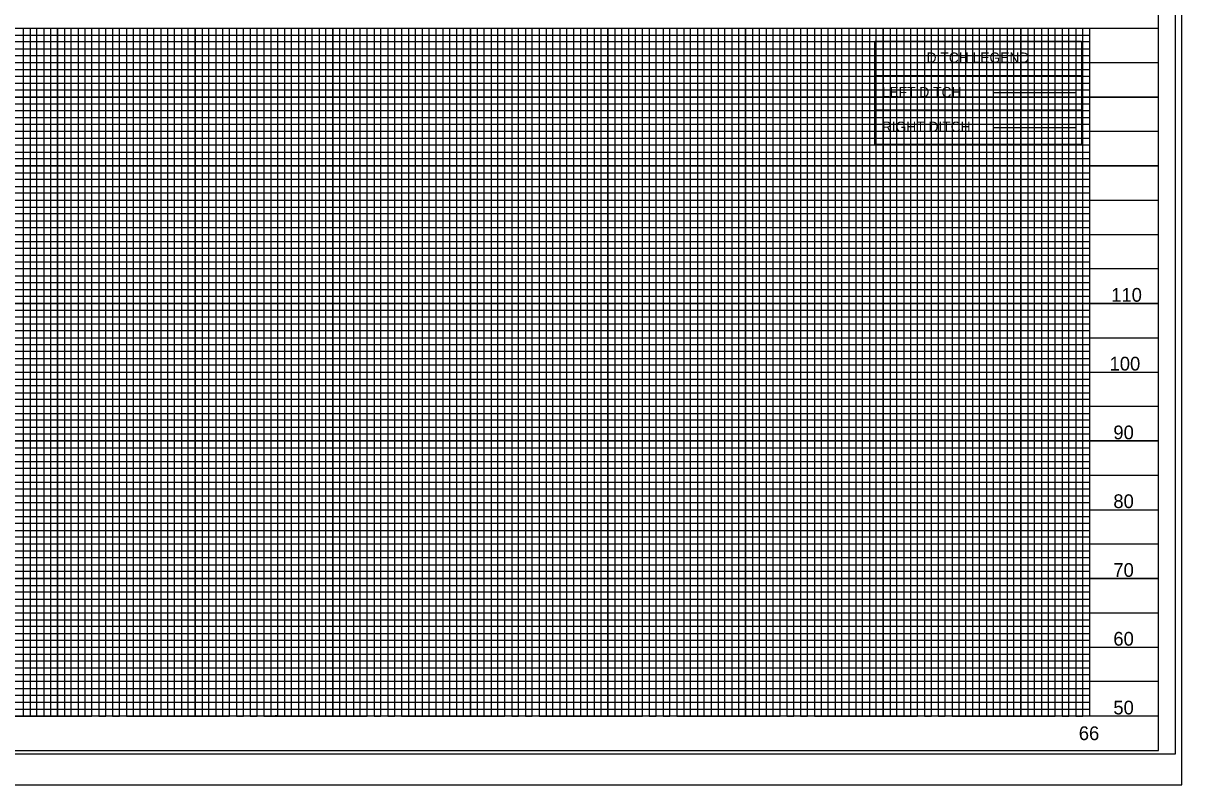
# Model space of a CAD drawing. Extents: x 2367101 to 2368930, y 803279 to 808979.
# Drawn here: x 2367943 to 2368785, y 803279 to 803833 of the extents above; entities that cross this region are included whole.
import ezdxf

# ---------------------------------------------------------------- set-up
doc = ezdxf.new("R2010")
doc.units = 0
for name, color, linetype in [('Old_Level_11', 7, 'Continuous'), ('Old_Level_12', 7, 'Continuous'), ('Old_Level_13', 7, 'Continuous'), ('Old_Level_15', 7, 'Continuous'), ('Old_Level_17', 7, 'Continuous'), ('Old_Level_19', 7, 'Continuous'), ('Old_Level_4', 7, 'Continuous'), ('Old_Level_5', 7, 'Continuous'), ('Old_Level_6', 7, 'Continuous'), ('Old_Level_60', 7, 'Continuous'), ('Old_Level_8', 7, 'Continuous'), ('Old_Level_9', 7, 'Continuous'), ('Text', 7, 'Continuous')]:
    doc.layers.add(name, color=color, linetype=linetype)

msp = doc.modelspace()

# ---------------------------------------------------------------- linework, layer by layer
at = {"layer": 'Old_Level_11'}
for p, q in [((2367967.97, 803828.98), (2368017.97, 803828.98)), ((2368067.97, 803828.98), (2368117.97, 803828.98)), ((2368167.97, 803828.98), (2368217.97, 803828.98)), ((2368267.97, 803828.98), (2368317.97, 803828.98)), ((2368367.97, 803828.98), (2368417.97, 803828.98)), ((2368467.97, 803828.98), (2368517.97, 803828.98)), ((2368567.97, 803828.98), (2368617.97, 803828.98)), ((2368667.97, 803828.98), (2368717.97, 803828.98)), ((2368667.97, 803328.98), (2368667.97, 803328.98))]:
    msp.add_line(p, q, dxfattribs=at)
for points in [[(2367917.97, 803328.98), (2367967.97, 803328.98), (2367967.97, 803828.98), (2368017.97, 803828.98), (2368017.97, 803328.98), (2368067.97, 803328.98), (2368067.97, 803828.98), (2368117.97, 803828.98), (2368117.97, 803328.98), (2368167.97, 803328.98), (2368167.97, 803828.98), (2368217.97, 803828.98), (2368217.97, 803328.98), (2368267.97, 803328.98), (2368267.97, 803828.98), (2368317.97, 803828.98), (2368317.97, 803328.98), (2368367.97, 803328.98), (2368367.97, 803828.98), (2368417.97, 803828.98), (2368417.97, 803328.98), (2368467.97, 803328.98), (2368467.97, 803828.98), (2368517.97, 803828.98), (2368517.97, 803328.98), (2368567.97, 803328.98), (2368567.97, 803828.98), (2368617.97, 803828.98), (2368617.97, 803328.98), (2368667.97, 803328.98), (2368667.97, 803328.98), (2368667.97, 803828.98), (2368717.97, 803828.98), (2368717.97, 803328.98)], [(2368767.97, 803778.98), (2367267.97, 803778.98)], [(2368767.97, 803728.98), (2367267.97, 803728.98), (2367267.97, 803678.98), (2368767.97, 803678.98)], [(2368767.97, 803628.98), (2367267.97, 803628.98), (2367267.97, 803578.98), (2368767.97, 803578.98)], [(2368767.97, 803528.98), (2367267.97, 803528.98), (2367267.97, 803478.98), (2368767.97, 803478.98)], [(2368767.97, 803428.98), (2367267.97, 803428.98), (2367267.97, 803428.98), (2367267.97, 803378.98), (2368767.97, 803378.98)], [(2368767.97, 803328.98), (2367267.97, 803328.98)]]:
    msp.add_lwpolyline(points, dxfattribs=at)
at = {"layer": 'Old_Level_12'}
for points in [[(2367892.97, 803828.98), (2367942.97, 803828.98), (2367942.97, 803328.98), (2367992.97, 803328.98), (2367992.97, 803828.98), (2368042.97, 803828.98), (2368042.97, 803328.98), (2368092.97, 803328.98), (2368092.97, 803828.98), (2368142.97, 803828.98), (2368142.97, 803328.98), (2368192.97, 803328.98), (2368192.97, 803828.98), (2368242.97, 803828.98), (2368242.97, 803328.98), (2368292.97, 803328.98), (2368292.97, 803828.98), (2368342.97, 803828.98), (2368342.97, 803328.98), (2368392.97, 803328.98), (2368392.97, 803828.98), (2368442.97, 803828.98), (2368442.97, 803328.98), (2368492.97, 803328.98), (2368492.97, 803828.98), (2368542.97, 803828.98), (2368542.97, 803328.98), (2368592.97, 803328.98), (2368592.97, 803828.98), (2368642.97, 803828.98), (2368642.97, 803328.98), (2368692.97, 803328.98), (2368692.97, 803828.98)], [(2367267.97, 803803.98), (2368767.97, 803803.98)], [(2368767.97, 803753.98), (2367267.97, 803753.98), (2367267.97, 803703.98), (2368767.97, 803703.98)], [(2368767.97, 803653.98), (2367267.97, 803653.98), (2367267.97, 803603.98), (2368767.97, 803603.98)], [(2368767.97, 803553.98), (2367267.97, 803553.98), (2367267.97, 803503.98), (2368767.97, 803503.98)], [(2368767.97, 803453.98), (2367267.97, 803453.98), (2367267.97, 803403.98), (2368767.97, 803403.98)], [(2368767.97, 803353.98), (2367267.97, 803353.98)]]:
    msp.add_lwpolyline(points, dxfattribs=at)
at = {"layer": 'Old_Level_13'}
for p, q in [((2367267.97, 803828.98), (2368767.86, 803828.98)), ((2367967.97, 803828.98), (2367967.97, 803328.98)), ((2368017.97, 803828.98), (2368017.97, 803328.98)), ((2368067.97, 803828.98), (2368067.97, 803328.98)), ((2368117.97, 803828.98), (2368117.97, 803328.98)), ((2368167.97, 803828.98), (2368167.97, 803328.98)), ((2368217.97, 803828.98), (2368217.97, 803328.98)), ((2368267.97, 803828.98), (2368267.97, 803328.98)), ((2368317.97, 803828.98), (2368317.97, 803328.98)), ((2368367.97, 803828.98), (2368367.97, 803328.98)), ((2368417.97, 803828.98), (2368417.97, 803328.98)), ((2368467.97, 803828.98), (2368467.97, 803328.98)), ((2368517.97, 803828.98), (2368517.97, 803328.98)), ((2368567.97, 803828.98), (2368567.97, 803328.98)), ((2368617.97, 803828.98), (2368617.97, 803328.98)), ((2368667.97, 803828.98), (2368667.97, 803328.98)), ((2368717.97, 803828.98), (2368717.97, 803328.98)), ((2367267.97, 803778.98), (2368767.86, 803778.98)), ((2367267.97, 803728.98), (2368767.86, 803728.98)), ((2367267.97, 803678.98), (2368767.86, 803678.98)), ((2367267.97, 803628.98), (2368767.86, 803628.98)), ((2367267.97, 803578.98), (2368767.86, 803578.98)), ((2367267.97, 803528.98), (2368767.86, 803528.98)), ((2367267.97, 803478.98), (2368767.86, 803478.98)), ((2367267.97, 803428.98), (2368767.86, 803428.98)), ((2367267.97, 803378.98), (2368767.86, 803378.98))]:
    msp.add_line(p, q, dxfattribs=at)
at = {"layer": 'Old_Level_15'}
msp.add_line((2367100.97, 803278.98), (2368784.97, 803278.98), dxfattribs=at)
at = {"layer": 'Old_Level_4'}
msp.add_lwpolyline([(2367113.97, 803301.43), (2368780.47, 803301.43), (2368780.47, 804356.53), (2367113.97, 804356.53)], close=True, dxfattribs=at)
at = {"layer": 'Old_Level_5'}
msp.add_lwpolyline([(2367317.97, 803828.98), (2368717.97, 803828.98), (2368717.97, 803328.98), (2367317.97, 803328.98)], close=True, dxfattribs=at)
at = {"layer": 'Old_Level_6'}
msp.add_lwpolyline([(2367100.97, 803278.98), (2368784.97, 803278.98), (2368784.97, 804378.98), (2367100.97, 804378.98)], close=True, dxfattribs=at)
at = {"layer": 'Old_Level_60'}
for points in [[(2368561.98, 803819.49), (2368711.98, 803819.49), (2368711.98, 803794.49), (2368561.98, 803794.49)], [(2368561.98, 803794.49), (2368711.98, 803794.49), (2368711.98, 803769.49), (2368561.98, 803769.49)], [(2368561.98, 803769.49), (2368711.98, 803769.49), (2368711.98, 803744.49), (2368561.98, 803744.49)]]:
    msp.add_lwpolyline(points, close=True, dxfattribs=at)
at = {"layer": 'Old_Level_8'}
for p, q in [((2367317.97, 803823.98), (2368717.97, 803823.98)), ((2368717.97, 803818.98), (2367317.97, 803818.98)), ((2367317.97, 803813.98), (2368717.97, 803813.98)), ((2368717.97, 803808.98), (2367317.97, 803808.98)), ((2367317.97, 803798.98), (2368717.97, 803798.98)), ((2368717.97, 803793.98), (2367317.97, 803793.98)), ((2367317.97, 803788.98), (2368717.97, 803788.98)), ((2368717.97, 803783.98), (2367317.97, 803783.98)), ((2367317.97, 803773.98), (2368717.97, 803773.98)), ((2368717.97, 803768.98), (2367317.97, 803768.98)), ((2367317.97, 803763.98), (2368717.97, 803763.98)), ((2368717.97, 803758.98), (2367317.97, 803758.98)), ((2367317.97, 803748.98), (2368717.97, 803748.98)), ((2368717.97, 803743.98), (2367317.97, 803743.98)), ((2367317.97, 803738.98), (2368717.97, 803738.98)), ((2368717.97, 803733.98), (2367317.97, 803733.98)), ((2367317.97, 803723.98), (2368717.97, 803723.98)), ((2368717.97, 803718.98), (2367317.97, 803718.98)), ((2367317.97, 803713.98), (2368717.97, 803713.98)), ((2368717.97, 803708.98), (2367317.97, 803708.98)), ((2367317.97, 803698.98), (2368717.97, 803698.98)), ((2368717.97, 803693.98), (2367317.97, 803693.98)), ((2367317.97, 803688.98), (2368717.97, 803688.98)), ((2368717.97, 803683.98), (2367317.97, 803683.98)), ((2367317.97, 803673.98), (2368717.97, 803673.98)), ((2368717.97, 803668.98), (2367317.97, 803668.98)), ((2367317.97, 803663.98), (2368717.97, 803663.98)), ((2368717.97, 803658.98), (2367317.97, 803658.98)), ((2367317.97, 803648.98), (2368717.97, 803648.98)), ((2368717.97, 803643.98), (2367317.97, 803643.98)), ((2367317.97, 803638.98), (2368717.97, 803638.98)), ((2368717.97, 803633.98), (2367317.97, 803634.13)), ((2367317.97, 803623.98), (2368717.97, 803623.98)), ((2368717.97, 803618.98), (2367317.97, 803618.98)), ((2367317.97, 803613.98), (2368717.97, 803613.98)), ((2368717.97, 803608.98), (2367317.97, 803608.98)), ((2367317.97, 803598.98), (2368717.97, 803598.98)), ((2368717.97, 803593.98), (2367317.97, 803593.98)), ((2367317.97, 803588.98), (2368717.97, 803588.98)), ((2368717.97, 803583.98), (2367317.97, 803583.98)), ((2367317.97, 803573.98), (2368717.97, 803573.98)), ((2368717.97, 803568.98), (2367317.97, 803568.98)), ((2367317.97, 803563.98), (2368717.97, 803563.98)), ((2368717.97, 803558.98), (2367317.97, 803558.98)), ((2367317.97, 803548.98), (2368717.97, 803548.98)), ((2368717.97, 803543.98), (2367317.97, 803543.98)), ((2367317.97, 803538.98), (2368717.97, 803538.98)), ((2368717.97, 803533.98), (2367317.97, 803533.98)), ((2367317.97, 803523.98), (2368717.97, 803523.98)), ((2368717.97, 803518.98), (2367317.97, 803518.98)), ((2367317.97, 803513.98), (2368717.97, 803513.98)), ((2368717.97, 803508.98), (2367317.97, 803508.98)), ((2367317.97, 803498.98), (2368717.97, 803498.98)), ((2368717.97, 803493.98), (2367317.97, 803493.98)), ((2367317.97, 803488.98), (2368717.97, 803488.98)), ((2368717.97, 803483.98), (2367317.97, 803483.98)), ((2367317.97, 803473.98), (2368717.97, 803473.98)), ((2368717.97, 803468.98), (2367317.97, 803468.98)), ((2367317.97, 803463.98), (2368717.97, 803463.98)), ((2368717.97, 803458.98), (2367317.97, 803458.98)), ((2367317.97, 803448.98), (2368717.97, 803448.98)), ((2368717.97, 803443.98), (2367317.97, 803443.98)), ((2367317.97, 803438.98), (2368717.97, 803438.98)), ((2368717.97, 803433.98), (2367317.97, 803433.98)), ((2367317.97, 803423.98), (2368717.97, 803423.98)), ((2368717.97, 803418.98), (2367317.97, 803418.98)), ((2367317.97, 803413.98), (2368717.97, 803413.98)), ((2368717.97, 803408.98), (2367317.97, 803408.98)), ((2367317.97, 803398.98), (2368717.97, 803398.98)), ((2368717.97, 803393.98), (2367317.97, 803393.98)), ((2367317.97, 803388.98), (2368717.97, 803388.98)), ((2368717.97, 803383.98), (2367317.97, 803383.98)), ((2367317.97, 803373.98), (2368717.97, 803373.98)), ((2368717.97, 803368.98), (2367317.97, 803368.98)), ((2367317.97, 803363.98), (2368717.97, 803363.98)), ((2368717.97, 803358.98), (2367317.97, 803358.98)), ((2367317.97, 803348.98), (2368717.97, 803348.98)), ((2368717.97, 803343.98), (2367317.97, 803343.98)), ((2367317.97, 803338.98), (2368717.97, 803338.98)), ((2367317.97, 803333.98), (2368717.97, 803333.98)), ((2368717.97, 803333.98), (2368717.97, 803333.98))]:
    msp.add_line(p, q, dxfattribs=at)
for points in [[(2367937.97, 803828.98), (2367947.97, 803828.98), (2367947.97, 803328.98), (2367952.97, 803328.98), (2367952.97, 803828.98), (2367957.97, 803828.98), (2367957.97, 803328.98), (2367962.97, 803328.98), (2367962.97, 803828.98), (2367972.97, 803828.98), (2367972.97, 803328.98), (2367972.97, 803328.98), (2367977.97, 803328.98), (2367977.97, 803828.98), (2367982.97, 803828.98), (2367982.97, 803328.98), (2367987.97, 803328.98), (2367987.97, 803828.98), (2367997.97, 803828.98), (2367997.97, 803328.98), (2368002.97, 803328.98), (2368002.97, 803828.98), (2368007.97, 803828.98), (2368007.97, 803328.98), (2368012.97, 803328.98), (2368012.97, 803828.98), (2368022.97, 803828.98), (2368022.97, 803328.98), (2368027.97, 803328.98), (2368027.97, 803828.98), (2368032.97, 803828.98), (2368032.97, 803328.98), (2368037.97, 803328.98), (2368037.97, 803828.98), (2368047.97, 803828.98), (2368047.97, 803328.98), (2368052.97, 803328.98), (2368052.97, 803828.98), (2368057.97, 803828.98), (2368057.97, 803328.98), (2368062.97, 803328.98), (2368062.97, 803828.98), (2368072.97, 803828.98), (2368072.97, 803328.98), (2368077.97, 803328.98), (2368077.97, 803828.98), (2368082.97, 803828.98), (2368082.97, 803328.98), (2368087.97, 803328.98), (2368087.97, 803828.98), (2368097.97, 803828.98), (2368097.97, 803328.98), (2368102.97, 803328.98), (2368102.97, 803828.98), (2368107.97, 803828.98), (2368107.97, 803328.98), (2368112.97, 803328.98), (2368112.97, 803828.98), (2368122.97, 803828.98), (2368122.97, 803328.98), (2368127.67, 803329.53), (2368127.97, 803328.98), (2368127.97, 803828.98), (2368132.97, 803828.98), (2368132.97, 803328.98), (2368137.97, 803328.98), (2368137.97, 803828.98), (2368147.97, 803828.98), (2368147.97, 803328.98), (2368152.97, 803328.98)], [(2368152.97, 803328.98), (2368152.97, 803828.98), (2368157.97, 803828.98), (2368157.97, 803328.98), (2368162.97, 803328.98), (2368162.97, 803828.98), (2368172.97, 803828.98), (2368172.97, 803328.98), (2368177.97, 803328.98), (2368177.97, 803828.98), (2368182.97, 803828.98), (2368182.97, 803328.98), (2368187.97, 803328.98), (2368187.97, 803828.98), (2368197.97, 803828.98), (2368197.97, 803328.98), (2368202.97, 803328.98), (2368202.97, 803828.98), (2368207.97, 803828.98), (2368207.97, 803328.98), (2368212.97, 803328.98), (2368212.97, 803828.98), (2368222.97, 803828.98), (2368222.97, 803328.98), (2368227.97, 803328.98), (2368227.97, 803828.98), (2368232.97, 803828.98), (2368232.97, 803328.98), (2368237.97, 803328.98), (2368237.97, 803828.98), (2368247.97, 803828.98), (2368247.97, 803328.98), (2368252.97, 803328.98), (2368252.97, 803828.98), (2368257.97, 803828.98), (2368257.97, 803328.98), (2368262.97, 803328.98), (2368262.97, 803828.98), (2368272.97, 803828.98), (2368272.97, 803328.98), (2368277.97, 803328.98), (2368277.97, 803828.98), (2368282.97, 803828.98), (2368282.97, 803328.98), (2368287.97, 803328.98), (2368287.97, 803828.98), (2368297.97, 803828.98), (2368297.97, 803328.98), (2368302.97, 803328.98), (2368302.97, 803828.98), (2368307.97, 803828.98), (2368307.97, 803328.98), (2368312.97, 803328.98), (2368312.97, 803828.98), (2368322.97, 803828.98), (2368322.97, 803328.98), (2368327.97, 803328.98), (2368327.97, 803828.98), (2368332.97, 803828.98), (2368332.97, 803328.98), (2368337.97, 803328.98), (2368337.97, 803828.98), (2368347.97, 803828.98), (2368347.97, 803328.98), (2368352.97, 803328.98), (2368352.97, 803828.98), (2368357.97, 803828.98), (2368357.97, 803328.98), (2368362.97, 803328.98), (2368362.97, 803828.98), (2368372.97, 803828.98), (2368372.97, 803328.98), (2368377.97, 803328.98), (2368377.97, 803828.98), (2368382.97, 803828.98), (2368382.97, 803328.98), (2368387.97, 803328.98), (2368387.97, 803828.98), (2368397.97, 803828.98), (2368397.97, 803328.98), (2368402.97, 803328.98), (2368402.97, 803828.98), (2368407.97, 803828.98), (2368407.97, 803328.98), (2368412.97, 803328.98), (2368412.97, 803828.98), (2368422.97, 803828.98), (2368422.97, 803328.98), (2368427.97, 803328.98), (2368427.97, 803828.98), (2368432.97, 803828.98), (2368432.97, 803328.98), (2368437.97, 803328.98), (2368437.97, 803828.98), (2368447.97, 803828.98), (2368447.97, 803328.98), (2368452.97, 803328.98), (2368452.97, 803828.98), (2368457.97, 803828.98), (2368457.97, 803328.98)], [(2368457.97, 803328.98), (2368462.97, 803328.98), (2368462.97, 803828.98), (2368472.97, 803828.98), (2368472.97, 803328.98), (2368477.97, 803328.98), (2368477.97, 803828.98), (2368482.97, 803828.98), (2368482.97, 803328.98), (2368487.97, 803328.98), (2368487.97, 803828.98), (2368497.97, 803828.98), (2368497.97, 803328.98), (2368502.97, 803328.98), (2368502.97, 803828.98), (2368507.97, 803828.98), (2368507.97, 803328.98), (2368512.97, 803328.98), (2368512.97, 803828.98), (2368522.97, 803828.98), (2368522.97, 803328.98), (2368527.97, 803328.98), (2368527.97, 803828.98), (2368532.97, 803828.98), (2368532.97, 803328.98), (2368537.97, 803328.98), (2368537.97, 803828.98), (2368547.97, 803828.98), (2368547.97, 803328.98), (2368552.97, 803328.98), (2368552.97, 803828.98), (2368557.97, 803828.98), (2368557.97, 803328.98), (2368562.97, 803328.98), (2368562.97, 803828.98), (2368572.97, 803828.98), (2368572.97, 803328.98), (2368577.97, 803328.98), (2368577.97, 803828.98), (2368582.97, 803828.98), (2368582.97, 803328.98), (2368587.97, 803328.98), (2368587.97, 803828.98), (2368597.97, 803828.98), (2368597.97, 803328.98), (2368602.97, 803328.98), (2368602.97, 803828.98), (2368607.97, 803828.98), (2368607.97, 803328.98), (2368612.97, 803328.98), (2368612.97, 803828.98), (2368622.97, 803828.98), (2368622.97, 803328.98), (2368627.97, 803328.98), (2368627.97, 803828.98), (2368632.97, 803828.98), (2368632.97, 803328.98), (2368637.97, 803328.98), (2368637.97, 803828.98), (2368647.97, 803828.98), (2368647.97, 803328.98), (2368652.97, 803328.98), (2368652.97, 803828.98), (2368657.97, 803828.98), (2368657.97, 803328.98), (2368662.97, 803328.98), (2368662.97, 803828.98), (2368672.97, 803828.98), (2368672.97, 803328.98), (2368677.97, 803328.98), (2368677.97, 803828.98), (2368682.97, 803828.98), (2368682.97, 803328.98), (2368687.97, 803328.98), (2368687.97, 803828.98), (2368697.97, 803828.98), (2368697.97, 803328.98), (2368702.97, 803328.98), (2368702.97, 803828.98), (2368707.97, 803828.98), (2368707.97, 803328.98), (2368712.97, 803328.98), (2368712.97, 803828.98), (2368717.97, 803828.98)]]:
    msp.add_lwpolyline(points, dxfattribs=at)
at = {"layer": 'Old_Level_9'}
for p, q in [((2367267.97, 803828.98), (2368767.97, 803828.98)), ((2368767.97, 803328.98), (2367267.97, 803328.98)), ((2367267.97, 803303.98), (2368767.97, 803303.98))]:
    msp.add_line(p, q, dxfattribs=at)
msp.add_lwpolyline([(2368767.97, 804353.98), (2367267.97, 804353.98), (2367267.97, 803303.98), (2368767.97, 803303.98)], close=True, dxfattribs=at)
at = {"layer": 'Text'}
for p, q in [((2368647.53, 803782.19), (2368707.53, 803782.19)), ((2368647.53, 803756.84), (2368707.53, 803756.84)), ((2368561.98, 803754.49), (2368561.98, 803754.49))]:
    msp.add_line(p, q, dxfattribs=at)

# ---------------------------------------------------------------- texts
at = {"layer": 'Old_Level_17'}
for s, p in [('110', (2368733.65, 803630.15)), ('100', (2368732.46, 803580.15)), ('90', (2368735.21, 803530.15)), ('80', (2368735.21, 803480.15)), ('70', (2368735.21, 803430.15)), ('60', (2368735.21, 803380.15)), ('50', (2368735.21, 803330.15))]:
    msp.add_text(s, height=10, dxfattribs=at).set_placement(p)
at = {"layer": 'Old_Level_19'}
msp.add_text('66', height=10, dxfattribs=at).set_placement((2368710.1, 803311.48))
at = {"layer": 'Text'}
for s, height, p in [('DITCH LEGEND', 7.5, (2368599.48, 803803.84)), ('LEFT DITCH', 7.485, (2368566.98, 803778.79)), ('RIGHT DITCH', 7.485, (2368566.98, 803753.59))]:
    msp.add_text(s, height=height, dxfattribs=at).set_placement(p)

doc.saveas('drawing.dxf')
